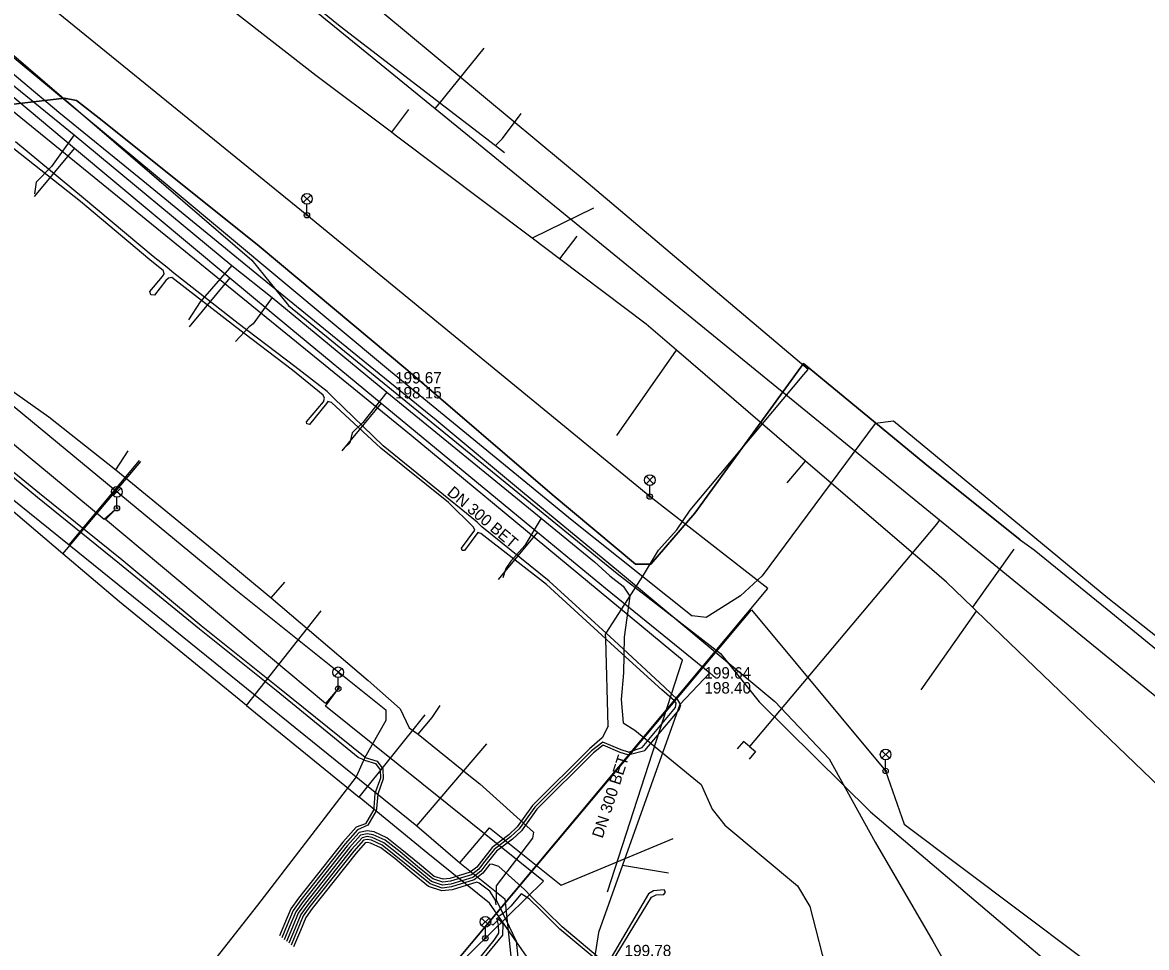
# Model space of a CAD drawing. Extents: x -598932 to -598196, y -1162210 to -1161504.
# Drawn here: x -598473 to -598394.1, y -1161970.7 to -1161905.8 of the extents above; entities that cross this region are included whole.
import ezdxf

# ---------------------------------------------------------------- set-up
doc = ezdxf.new("R2010")
doc.units = 0
for name, color, linetype in [('Vrstva 1', 7, 'Continuous'), ('Vrstva 12', 7, 'Continuous'), ('Vrstva 13', 7, 'Continuous'), ('Vrstva 14', 7, 'Continuous'), ('Vrstva 16', 7, 'Continuous'), ('Vrstva 33', 7, 'Continuous'), ('Vrstva 37', 7, 'Continuous'), ('Vrstva 42', 7, 'Continuous'), ('Vrstva 53', 7, 'Continuous'), ('Vrstva 55', 7, 'Continuous'), ('Vrstva 58', 7, 'Continuous'), ('Vrstva 9', 7, 'Continuous')]:
    doc.layers.add(name, color=color, linetype=linetype)

msp = doc.modelspace()

# ---------------------------------------------------------------- linework, layer by layer
at = {"layer": 'Vrstva 1'}
for p, q in [((-598432.9, -1161918.86), (-598437.222, -1161920.966)), ((-598431.28, -1161934.8), (-598427.09, -1161928.823)), ((-598403.43, -1161942.78), (-598406.33, -1161946.856)), ((-598409.92, -1161952.64), (-598406.049, -1161947.126))]:
    msp.add_line(p, q, dxfattribs=at)
at = {"layer": 'Vrstva 12'}
for p, q in [((-598466.42, -1161937.21), (-598465.54, -1161935.89)), ((-598455.53, -1161946.19), (-598454.57, -1161945.1)), ((-598455.53, -1161946.19), (-598448.71, -1161952))]:
    msp.add_line(p, q, dxfattribs=at)
for points in [[(-598530.18, -1161910.6), (-598528.12, -1161912.39), (-598513.23, -1161925.26), (-598505.92, -1161931.22), (-598502.39, -1161926.92), (-598497.84, -1161929.5), (-598487.53, -1161917.27), (-598477.22, -1161905.04), (-598476.26, -1161905.87), (-598456.87, -1161922.52), (-598454.31, -1161925.7), (-598431.25, -1161944.5), (-598424.01, -1161950.11), (-598421.3, -1161953.5), (-598413.48, -1161961.2), (-598396.81, -1161975.36)], [(-598475.64, -1161930.32), (-598471.11, -1161933.5), (-598466.42, -1161937.21)], [(-598466.42, -1161937.21), (-598459.26, -1161943.09), (-598455.53, -1161946.19)], [(-598448.71, -1161952), (-598446.48, -1161953.99), (-598445.84, -1161955.32), (-598445.22, -1161955.77)], [(-598445.22, -1161955.77), (-598444.23, -1161954.59), (-598443.67, -1161953.76)], [(-598445.22, -1161955.77), (-598441.66, -1161958.64), (-598440.88, -1161959.25), (-598437.12, -1161962.64), (-598437.19, -1161963.05), (-598439.74, -1161966.4), (-598439.74, -1161967.38), (-598438.83, -1161969.24), (-598438.33, -1161970.29), (-598437.87, -1161974.77), (-598437.22, -1161978.66), (-598436.48, -1161982.5), (-598435.66, -1161986.28), (-598434.35, -1161995.42), (-598434.53, -1161998.2), (-598434.36, -1161998.39), (-598434.1, -1161998.45), (-598432.39, -1161998.79), (-598432.12, -1161998.84), (-598421.61, -1162000.07), (-598421.01, -1162000.03), (-598420.77, -1161999.59), (-598418.4, -1161984.79)]]:
    msp.add_lwpolyline(points, dxfattribs=at)
at = {"layer": 'Vrstva 13'}
for p, q in [((-598470.13, -1161943.11), (-598477.74, -1161936.64)), ((-598470.13, -1161943.11), (-598464.67, -1161936.64)), ((-598457.24, -1161953.75), (-598452.01, -1161947.11)), ((-598457.24, -1161953.75), (-598459.94, -1161951.55)), ((-598457.24, -1161953.75), (-598449.34, -1161960.19)), ((-598449.34, -1161960.19), (-598444.72, -1161954.4))]:
    msp.add_line(p, q, dxfattribs=at)
for points in [[(-598459.94, -1161951.55), (-598466.16, -1161946.47), (-598470.13, -1161943.11)], [(-598431.09, -1161986.13), (-598433.1, -1161985.8), (-598432.54, -1161978.26), (-598433.93, -1161976.6), (-598440.21, -1161967.61), (-598444.52, -1161964.12), (-598449.34, -1161960.19)]]:
    msp.add_lwpolyline(points, dxfattribs=at)
at = {"layer": 'Vrstva 14'}
for points in [[(-598589.515, -1161793.152), (-598565.413, -1161812.812), (-598551.541, -1161824.13), (-598545.495, -1161829.063), (-598526.422, -1161844.625), (-598503.906, -1161862.996), (-598485.507, -1161878.008), (-598479.302, -1161883.071), (-598460.805, -1161898.163), (-598459.029, -1161899.612), (-598444.013, -1161911.864), (-598408.629, -1161940.734), (-598391.372, -1161954.815), (-598364.721, -1161976.56), (-598364.173, -1161977.007)], [(-598444.013, -1161911.864), (-598443.745, -1161911.535), (-598440.572, -1161907.647)], [(-598408.629, -1161940.734), (-598408.787, -1161940.928), (-598408.977, -1161941.161), (-598421.968, -1161956.627), (-598421.543, -1161956.984), (-598421.988, -1161957.512)], [(-598421.968, -1161956.627), (-598422.393, -1161956.27), (-598422.837, -1161956.798)]]:
    msp.add_lwpolyline(points, dxfattribs=at)
at = {"layer": 'Vrstva 16'}
for p, q in [((-598469.32, -1161914.66), (-598472.14, -1161918.04)), ((-598458.41, -1161923.75), (-598461.28, -1161927.19)), ((-598447.8, -1161932.54), (-598450.57, -1161935.89)), ((-598436.85, -1161941.58), (-598439.59, -1161944.9)), ((-598430.88, -1161964.96), (-598427.66, -1161965.48))]:
    msp.add_line(p, q, dxfattribs=at)
for points in [[(-598623.45, -1161841.93), (-598614.74, -1161848.93), (-598608.74, -1161854.09), (-598596.77, -1161885.91), (-598521.8, -1161947.46), (-598518.56, -1161943.92), (-598508.46, -1161933.01), (-598496.44, -1161920), (-598487.04, -1161908.55), (-598482.77, -1161903.44), (-598475.7, -1161909.33), (-598469.32, -1161914.66), (-598458.41, -1161923.75), (-598454.13, -1161927.31), (-598447.8, -1161932.54), (-598436.85, -1161941.58), (-598432.08, -1161945.52), (-598424.74, -1161951.46)], [(-598460.06, -1161898.48), (-598450.67, -1161906.11), (-598439.78, -1161914.48), (-598439.15, -1161914.97)], [(-598439.78, -1161914.48), (-598439.3, -1161913.98), (-598437.98, -1161912.22)], [(-598424.35, -1161951.82), (-598424.74, -1161951.46), (-598426.85, -1161953.67), (-598430.88, -1161964.96), (-598432.57, -1161969.68), (-598435.12, -1161986), (-598435.65, -1161989.44)]]:
    msp.add_lwpolyline(points, dxfattribs=at)
at = {"layer": 'Vrstva 33'}
for p, q in [((-598453.275, -1161917.945), (-598452.745, -1161918.475)), ((-598453.275, -1161918.475), (-598452.745, -1161917.945)), ((-598453.01, -1161919.36), (-598453.01, -1161918.585)), ((-598429.225, -1161937.675), (-598428.695, -1161938.205)), ((-598429.225, -1161938.205), (-598428.695, -1161937.675)), ((-598466.605, -1161938.495), (-598466.075, -1161939.025)), ((-598466.605, -1161939.025), (-598466.075, -1161938.495)), ((-598428.96, -1161939.09), (-598428.96, -1161938.315)), ((-598466.34, -1161939.91), (-598466.34, -1161939.135)), ((-598451.085, -1161951.155), (-598450.555, -1161951.685)), ((-598451.085, -1161951.685), (-598450.555, -1161951.155)), ((-598450.82, -1161952.57), (-598450.82, -1161951.795)), ((-598412.685, -1161956.925), (-598412.155, -1161957.455)), ((-598412.685, -1161957.455), (-598412.155, -1161956.925)), ((-598412.42, -1161958.34), (-598412.42, -1161957.565)), ((-598440.761, -1161968.656), (-598440.231, -1161969.186)), ((-598440.761, -1161969.186), (-598440.231, -1161968.656)), ((-598440.496, -1161970.071), (-598440.496, -1161969.296))]:
    msp.add_line(p, q, dxfattribs=at)
for centre, radius in [((-598453.01, -1161918.21), 0.375), ((-598453.01, -1161919.36), 0.19), ((-598453.01, -1161919.36), 0.05), ((-598428.96, -1161937.94), 0.375), ((-598466.34, -1161938.76), 0.375), ((-598428.96, -1161939.09), 0.19), ((-598428.96, -1161939.09), 0.05), ((-598466.34, -1161939.91), 0.19), ((-598466.34, -1161939.91), 0.05), ((-598450.82, -1161951.42), 0.375), ((-598450.82, -1161952.57), 0.19), ((-598450.82, -1161952.57), 0.05), ((-598412.42, -1161957.19), 0.375), ((-598412.42, -1161958.34), 0.19), ((-598412.42, -1161958.34), 0.05), ((-598440.496, -1161968.921), 0.375), ((-598440.496, -1161970.071), 0.19), ((-598440.496, -1161970.071), 0.05)]:
    msp.add_circle(centre, radius, dxfattribs=at)
at = {"layer": 'Vrstva 37'}
for p, q in [((-598469.69, -1161942.486), (-598464.747, -1161936.566)), ((-598469.69, -1161942.486), (-598445.305, -1161962.191)), ((-598445.305, -1161962.191), (-598440.385, -1161956.428)), ((-598445.305, -1161962.191), (-598442.289, -1161964.79))]:
    msp.add_line(p, q, dxfattribs=at)
for points in [[(-598508.056, -1161900.133), (-598492.103, -1161912.672), (-598497.677, -1161919.914), (-598469.69, -1161942.486)], [(-598442.289, -1161964.79), (-598440.214, -1161962.333), (-598435.179, -1161966.364), (-598427.322, -1161963.075)], [(-598442.289, -1161964.79), (-598439.127, -1161967.301), (-598437.079, -1161987.046), (-598431.386, -1161987.963)]]:
    msp.add_lwpolyline(points, dxfattribs=at)
at = {"layer": 'Vrstva 42'}
for points in [[(-598431.877, -1161955.189), (-598432.048, -1161949.071), (-598432.058, -1161948.715), (-598432.033, -1161948.676), (-598429.41, -1161944.597), (-598428.349, -1161942.848), (-598427.073, -1161941.433), (-598426.127, -1161940.048), (-598418.159, -1161930.541), (-598417.856, -1161930.173), (-598433.28, -1161917.143), (-598449.489, -1161903.651), (-598449.011, -1161903.074), (-598449.165, -1161902.947), (-598449.319, -1161902.819), (-598449.798, -1161903.397), (-598451.206, -1161902.284), (-598458.89, -1161896.076), (-598463.485, -1161892.268), (-598463.712, -1161892.08), (-598476.041, -1161881.863)], [(-598475, -1161911.73), (-598470.01, -1161911.14), (-598469.17, -1161911.32), (-598467.37, -1161912.72), (-598456.37, -1161921.52), (-598445.93, -1161930.26), (-598435.81, -1161938.94), (-598429.96, -1161943.83), (-598428.9, -1161943.83), (-598425.81, -1161940.25), (-598418.18, -1161929.76), (-598416.59, -1161931.06), (-598409.66, -1161936.77), (-598402.99, -1161942.14), (-598401.99, -1161942.83), (-598396.87, -1161946.99), (-598384.32, -1161957.25), (-598373, -1161966.76), (-598360.95, -1161976.47), (-598360.49, -1161977.47), (-598350.6, -1161985.5), (-598337.84, -1161995.92)], [(-598430.506, -1161957.205), (-598429.32, -1161956.9), (-598426.91, -1161954.05), (-598426.79, -1161953.71), (-598427, -1161953.36), (-598427.93, -1161952.46), (-598431.47, -1161949.19), (-598432.033, -1161948.676), (-598436.02, -1161945.04), (-598440.74, -1161941.22), (-598441.08, -1161940.9), (-598447.66, -1161935.54), (-598451.15, -1161932.16), (-598451.59, -1161931.73), (-598453.85, -1161929.97), (-598457.83, -1161926.96), (-598462.35, -1161923.43), (-598462.82, -1161923.02), (-598463.8, -1161922.25), (-598468.68, -1161918.17), (-598473.46, -1161914.22)], [(-598453.016, -1161934.001), (-598453.05, -1161933.855), (-598451.85, -1161932.45), (-598451.79, -1161932.2), (-598451.87, -1161931.99), (-598454.03, -1161930.23), (-598458.02, -1161927.19), (-598462.49, -1161923.72), (-598462.715, -1161923.785), (-598462.9, -1161923.95), (-598463.709, -1161924.965), (-598463.965, -1161924.942), (-598464.041, -1161924.713), (-598463.152, -1161923.665), (-598463.033, -1161923.466), (-598463.07, -1161923.25), (-598464.03, -1161922.48), (-598468.9, -1161918.4), (-598473.563, -1161914.702)], [(-598430.448, -1161957.013), (-598429.5, -1161956.69), (-598427.15, -1161953.9), (-598427.11, -1161953.59), (-598427.24, -1161953.43), (-598428.11, -1161952.65), (-598431.7, -1161949.39), (-598432.048, -1161949.071), (-598436.21, -1161945.26), (-598440.81, -1161941.68), (-598441.019, -1161941.617), (-598441.957, -1161942.889), (-598442.126, -1161942.883), (-598442.177, -1161942.71), (-598441.24, -1161941.45), (-598441.32, -1161941.23), (-598443.08, -1161939.51), (-598447.83, -1161935.71), (-598451.3, -1161932.5), (-598451.539, -1161932.43), (-598451.634, -1161932.577), (-598452.843, -1161934.037), (-598453.016, -1161934.001)], [(-598448.918, -1161957.403), (-598455.06, -1161952.46), (-598460.42, -1161948.15), (-598466, -1161943.54), (-598471.78, -1161938.87), (-598477.58, -1161934.15)], [(-598448.976, -1161957.595), (-598449.417, -1161957.398), (-598455.18, -1161952.7), (-598460.55, -1161948.4), (-598466.16, -1161943.81), (-598471.92, -1161939.15), (-598477.7, -1161934.4)], [(-598431.877, -1161955.189), (-598432.297, -1161956.009), (-598433.198, -1161956.797), (-598437.18, -1161960.759), (-598438.268, -1161962.266), (-598438.856, -1161962.816), (-598440.015, -1161963.7), (-598440.774, -1161964.665), (-598441.101, -1161965.086), (-598441.561, -1161965.448), (-598442.989, -1161965.886), (-598443.455, -1161965.941), (-598444.081, -1161965.733), (-598445.123, -1161964.879), (-598446.357, -1161963.867), (-598447.417, -1161963.035), (-598448.307, -1161962.623), (-598448.783, -1161962.543), (-598449.35, -1161962.657), (-598450.18, -1161963.59), (-598453.277, -1161967.499), (-598453.793, -1161968.221), (-598454.211, -1161969.212), (-598454.604, -1161970.177)], [(-598430.448, -1161957.013), (-598430.963, -1161956.855), (-598432.256, -1161956.317), (-598433.057, -1161956.939), (-598437.027, -1161960.889), (-598438.117, -1161962.399), (-598438.727, -1161962.969), (-598439.867, -1161963.839), (-598440.616, -1161964.788), (-598440.958, -1161965.228), (-598441.467, -1161965.627), (-598442.948, -1161966.083), (-598443.476, -1161966.145), (-598444.179, -1161965.911), (-598445.25, -1161965.034), (-598446.482, -1161964.023), (-598447.522, -1161963.207), (-598448.367, -1161962.816), (-598448.78, -1161962.746), (-598449.246, -1161962.84), (-598450.027, -1161963.719), (-598453.117, -1161967.619), (-598453.617, -1161968.319), (-598454.027, -1161969.289), (-598454.447, -1161970.299)], [(-598430.506, -1161957.205), (-598431.031, -1161957.043), (-598432.238, -1161956.541), (-598432.916, -1161957.081), (-598436.874, -1161961.019), (-598437.966, -1161962.532), (-598438.598, -1161963.122), (-598439.719, -1161963.978), (-598440.458, -1161964.91), (-598440.816, -1161965.37), (-598441.371, -1161965.807), (-598442.907, -1161966.279), (-598443.497, -1161966.349), (-598444.277, -1161966.089), (-598445.377, -1161965.189), (-598446.607, -1161964.179), (-598447.627, -1161963.379), (-598448.427, -1161963.009), (-598448.777, -1161962.949), (-598449.141, -1161963.023), (-598449.874, -1161963.848), (-598452.957, -1161967.739), (-598453.441, -1161968.417), (-598453.843, -1161969.366), (-598454.287, -1161970.425)], [(-598448.976, -1161957.595), (-598448.207, -1161957.825), (-598447.885, -1161958.254), (-598447.858, -1161958.854), (-598448.246, -1161959.918), (-598448.322, -1161960.899), (-598448.324, -1161961.049), (-598448.902, -1161962.046), (-598449.56, -1161962.291), (-598450.487, -1161963.333), (-598453.597, -1161967.258), (-598454.144, -1161968.024), (-598454.58, -1161969.057), (-598454.936, -1161969.915)], [(-598448.918, -1161957.403), (-598448.087, -1161957.653), (-598447.689, -1161958.184), (-598447.656, -1161958.884), (-598448.048, -1161959.96), (-598448.127, -1161960.976), (-598448.15, -1161961.149), (-598448.732, -1161962.152), (-598449.455, -1161962.474), (-598450.333, -1161963.462), (-598453.437, -1161967.378), (-598453.968, -1161968.123), (-598454.396, -1161969.134), (-598454.778, -1161970.054)], [(-598437.289, -1161967.156), (-598437.757, -1161966.659), (-598439.547, -1161965.049), (-598439.977, -1161964.899), (-598440.181, -1161964.881), (-598440.673, -1161965.512), (-598441.277, -1161965.988), (-598442.866, -1161966.475), (-598443.518, -1161966.553), (-598444.375, -1161966.267), (-598447.732, -1161963.551), (-598448.487, -1161963.202), (-598448.798, -1161963.152), (-598449.034, -1161963.205), (-598449.721, -1161963.976), (-598452.797, -1161967.86), (-598453.266, -1161968.515), (-598454.117, -1161970.56)], [(-598439.731, -1161967.737), (-598439.787, -1161967.399), (-598440.187, -1161966.769), (-598440.927, -1161966.209), (-598441.085, -1161966.138), (-598442.824, -1161966.671), (-598443.539, -1161966.757), (-598444.473, -1161966.445), (-598445.631, -1161965.499), (-598446.857, -1161964.491), (-598447.837, -1161963.723), (-598448.547, -1161963.395), (-598448.771, -1161963.356), (-598448.931, -1161963.388), (-598449.567, -1161964.105), (-598452.637, -1161967.98), (-598453.09, -1161968.614), (-598453.474, -1161969.521), (-598453.959, -1161970.685)], [(-598430.416, -1161982.03), (-598431.83, -1161981.47), (-598432.42, -1161981.29), (-598432.68, -1161981.07), (-598432.72, -1161980.75), (-598432.54, -1161978.3), (-598432.3, -1161974.44), (-598431.93, -1161972.67), (-598431.97, -1161972.27), (-598432.09, -1161972.13), (-598432.28, -1161971.94), (-598435.27, -1161969.44), (-598436.637, -1161968.083), (-598437.425, -1161967.302), (-598437.977, -1161966.949), (-598438.717, -1161967.819), (-598439.237, -1161968.329), (-598439.502, -1161968.515)], [(-598430.377, -1161981.794), (-598431.79, -1161981.22), (-598432.21, -1161981.02), (-598432.38, -1161980.86), (-598432.45, -1161980.74), (-598432.337, -1161978.491), (-598432.05, -1161974.44), (-598431.7, -1161972.79), (-598431.62, -1161972.47), (-598431.71, -1161972.039), (-598431.642, -1161971.791), (-598428.842, -1161967.183), (-598428.517, -1161967.039), (-598427.976, -1161967.002), (-598427.854, -1161966.847), (-598427.963, -1161966.689), (-598428.71, -1161966.74), (-598429.06, -1161966.97), (-598431.84, -1161971.71), (-598431.91, -1161971.83), (-598432.13, -1161971.78), (-598435.12, -1161969.27), (-598437.289, -1161967.156)], [(-598439.66, -1161968.625), (-598439.55, -1161968.75), (-598439.28, -1161969.06), (-598439.29, -1161969.87), (-598446.31, -1161978.4), (-598453.81, -1161987.51), (-598460.24, -1161995.18), (-598460.87, -1161995.6), (-598469.91, -1161994.3), (-598476.38, -1161993.12), (-598477.91, -1161993.09), (-598480.04, -1161992.61), (-598481.09, -1161992.03), (-598492.38, -1161989.84), (-598502.86, -1161988.32), (-598511.83, -1161986.57), (-598515.52, -1161985.57), (-598515.545, -1161985.865)], [(-598444.52, -1161974.41), (-598443.93, -1161974.58), (-598443.48, -1161974.48), (-598443.06, -1161974.08), (-598441.56, -1161972.28), (-598439.877, -1161970.219), (-598439.557, -1161969.729), (-598439.567, -1161969.139), (-598439.697, -1161968.669)], [(-598440.067, -1161969.054), (-598439.98, -1161969.15), (-598439.553, -1161968.746)]]:
    msp.add_lwpolyline(points, dxfattribs=at)
at = {"layer": 'Vrstva 53'}
for points in [[(-598487.007, -1161918.346), (-598483.42, -1161914.35), (-598478.45, -1161909.14), (-598476.3, -1161906.6), (-598475.63, -1161906.62), (-598462.53, -1161917.47), (-598447.16, -1161930.29), (-598434.4, -1161940.74), (-598425.99, -1161947.45)], [(-598487.83, -1161917.67), (-598489.28, -1161919.53), (-598487.17, -1161921.48), (-598482.98, -1161924.3), (-598481.33, -1161925.12), (-598480.75, -1161926.42), (-598479.43, -1161927.93), (-598468.75, -1161936.76), (-598458, -1161945.63), (-598447.48, -1161954.05), (-598447.47, -1161954.8), (-598448.95, -1161957.4), (-598449.56, -1161958.75), (-598456.47, -1161967.76), (-598467.12, -1161981.29), (-598467.86, -1161982.68), (-598467.93, -1161985.14), (-598467.78, -1161986.21)], [(-598288.075, -1161982.159), (-598290.85, -1161992.93), (-598301.83, -1161997.6), (-598307.07, -1161998.86), (-598314.12, -1162000.12), (-598325.21, -1162002.33), (-598329.76, -1162001.89), (-598334.84, -1161997.66), (-598348.23, -1161986.57), (-598360.56, -1161976.57), (-598362.37, -1161974.12), (-598374.43, -1161964.53), (-598384.11, -1161956.28), (-598396.83, -1161946.22), (-598401.41, -1161942.44), (-598411.87, -1161933.81), (-598413.16, -1161933.96), (-598421.08, -1161944.66), (-598422.6, -1161946.06), (-598425.01, -1161947.58), (-598425.99, -1161947.45)]]:
    msp.add_lwpolyline(points, dxfattribs=at)
at = {"layer": 'Vrstva 55'}
for points in [[(-598445.98, -1161975.82), (-598420.69, -1161945.55), (-598428.96, -1161939.09), (-598453.01, -1161919.36), (-598497.77, -1161883), (-598523.06, -1161862.52), (-598551.11, -1161839.54), (-598586.36, -1161810.66), (-598588.39, -1161808.928), (-598593.724, -1161815.599)], [(-598446.033, -1161975.79), (-598445.086, -1161974.588), (-598436.417, -1161966.065), (-598451.7, -1161953.79), (-598450.76, -1161952.48), (-598451.7, -1161953.6), (-598467.14, -1161940.71), (-598466.48, -1161940.05), (-598467.23, -1161940.71), (-598485.3, -1161925.75), (-598484.73, -1161925.09), (-598485.3, -1161925.66), (-598490.19, -1161923.49), (-598495.27, -1161917.38), (-598499.78, -1161913.86)], [(-598445.98, -1161975.82), (-598421.82, -1161947.05), (-598412.42, -1161958.34), (-598411.119, -1161962.069), (-598390.7, -1161977.42), (-598380.95, -1161977.42), (-598377.637, -1161979.983)]]:
    msp.add_lwpolyline(points, dxfattribs=at)
at = {"layer": 'Vrstva 58'}
for p, q in [((-598469.35, -1161913.72), (-598458.27, -1161922.88)), ((-598458.27, -1161922.88), (-598455.45, -1161925.14)), ((-598455.45, -1161925.14), (-598447.41, -1161931.78)), ((-598447.41, -1161931.78), (-598436.58, -1161940.62))]:
    msp.add_line(p, q, dxfattribs=at)
for points in [[(-598475.05, -1161908.26), (-598470.42, -1161912.13), (-598464.77, -1161916.72), (-598456.52, -1161923.47), (-598449.33, -1161929.34), (-598443.95, -1161933.71), (-598437.88, -1161938.77), (-598431.16, -1161944.32), (-598424.09, -1161950.22), (-598420.19, -1161953.47), (-598416.38, -1161957.49), (-598413.15, -1161963.34), (-598409.1, -1161970.29), (-598404.58, -1161978.33), (-598403.49, -1161987.03), (-598403.08, -1161997.66), (-598401.955, -1161999.524), (-598398.63, -1162005.03), (-598397.24, -1162007.27), (-598395.46, -1162010.14)], [(-598474.81, -1161909.14), (-598474.12, -1161909.85), (-598469.35, -1161913.72)], [(-598467.37, -1161912.72), (-598469.17, -1161911.32), (-598470.01, -1161911.14), (-598475, -1161911.73), (-598479.15, -1161912.14), (-598480.72, -1161912.35), (-598481.98, -1161912.74), (-598483.61, -1161914.46)], [(-598402.99, -1161942.14), (-598409.66, -1161936.77), (-598416.59, -1161931.06), (-598418.18, -1161929.76), (-598425.81, -1161940.25), (-598428.9, -1161943.83), (-598429.96, -1161943.83), (-598435.81, -1161938.94), (-598445.93, -1161930.26), (-598456.37, -1161921.52), (-598467.37, -1161912.72)], [(-598469.35, -1161913.72), (-598470.94, -1161915.95), (-598472.01, -1161917.03), (-598472.13, -1161917.85)], [(-598458.27, -1161922.88), (-598460.5, -1161925.43), (-598461.33, -1161926.7)], [(-598455.45, -1161925.14), (-598456.78, -1161926.98), (-598457.07, -1161927.2), (-598458.03, -1161928.22)], [(-598447.41, -1161931.78), (-598449.08, -1161933.91), (-598449.84, -1161934.63), (-598450, -1161935.32), (-598450.38, -1161935.68)], [(-598436.58, -1161940.62), (-598437.72, -1161942.52), (-598438.72, -1161943.63), (-598439.05, -1161944.15), (-598439.27, -1161944.8)], [(-598436.58, -1161940.62), (-598432.84, -1161943.67), (-598431.77, -1161944.65)], [(-598431.77, -1161944.65), (-598430.83, -1161945.38), (-598430.36, -1161946.08), (-598430.77, -1161948.95), (-598430.8, -1161951.45), (-598430.96, -1161953.32), (-598430.82, -1161954.97), (-598430.01, -1161955.47), (-598425.37, -1161959.29), (-598424.59, -1161961.01), (-598423.7, -1161962.15), (-598418.59, -1161966.41)], [(-598418.59, -1161966.41), (-598417.73, -1161967.86), (-598416.45, -1161972.86), (-598416.98, -1161974.46), (-598418.38, -1161984.79), (-598418.54, -1161985.87), (-598419.02, -1161988.61)]]:
    msp.add_lwpolyline(points, dxfattribs=at)
at = {"layer": 'Vrstva 9'}
for p, q in [((-598445.71, -1161934.82), (-598480.59, -1161906.42)), ((-598445.884, -1161911.938), (-598447.087, -1161913.536)), ((-598434.086, -1161920.824), (-598435.289, -1161922.422)), ((-598426.66, -1161950.58), (-598445.71, -1161934.82)), ((-598419.334, -1161938.13), (-598418.03, -1161936.614)), ((-598431.94, -1161966.82), (-598426.66, -1161950.58))]:
    msp.add_line(p, q, dxfattribs=at)
for points in [[(-598452.38, -1161909.55), (-598458.098, -1161905.125), (-598462.179, -1161901.967), (-598462.218, -1161901.937), (-598472.08, -1161894.305), (-598477.545, -1161890.076), (-598479.62, -1161888.47)], [(-598429.21, -1161927), (-598435.289, -1161922.422), (-598437.222, -1161920.966), (-598446.815, -1161913.741), (-598447.087, -1161913.536), (-598452.38, -1161909.55)], [(-598408.15, -1161945.11), (-598409.704, -1161943.773), (-598411.114, -1161942.56), (-598418.03, -1161936.614), (-598427.09, -1161928.823), (-598429.21, -1161927)], [(-598390.86, -1161961.7), (-598406.049, -1161947.126), (-598406.33, -1161946.856), (-598408.15, -1161945.11)]]:
    msp.add_lwpolyline(points, dxfattribs=at)

# ---------------------------------------------------------------- texts
at = {"layer": 'Vrstva 12'}
for s, p in [('199.67', (-598446.829, -1161931.159)), ('198.15', (-598446.829, -1161932.209)), ('199.64', (-598425.13, -1161951.86)), ('198.40', (-598425.13, -1161952.91)), ('199.78', (-598430.727, -1161971.34))]:
    msp.add_text(s, height=0.8, dxfattribs=at).set_placement(p)
for rotation, p in [(320, (-598443.24, -1161938.912)), (72, (-598432.277, -1161963.112))]:
    msp.add_text('DN 300 BET', height=0.8, rotation=rotation, dxfattribs=at).set_placement(p)

doc.saveas('drawing.dxf')
